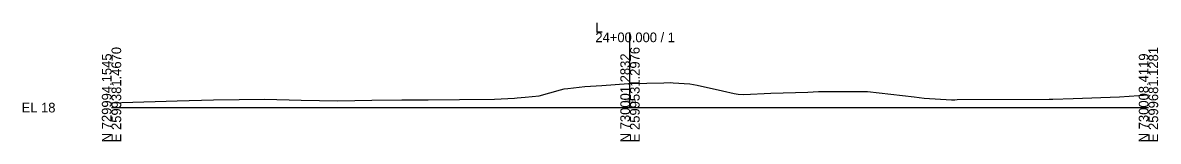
# Model space of a CAD drawing. Extents: x -26 to 3303, y -10 to 9555.
# Drawn here: x 1974.3 to 2302.8, y 7990.3 to 8024.5 of the extents above; entities that cross this region are included whole.
import ezdxf

# ---------------------------------------------------------------- set-up
doc = ezdxf.new("R2010")
doc.units = 0
for name, color, linetype in [('Exist Cross Section Cell', 7, 'Continuous'), ('Exist XS Center Line Elevation Label', 7, 'Continuous'), ('Exist XS Ground Line', 7, 'Continuous')]:
    doc.layers.add(name, color=color, linetype=linetype)

msp = doc.modelspace()

# ---------------------------------------------------------------- linework, layer by layer
at = {"layer": 'Exist Cross Section Cell'}
for p, q in [((2150, 8000), (2150, 8021.65)), ((2000, 8000), (2150, 8000)), ((2150, 8000), (2300, 8000))]:
    msp.add_line(p, q, dxfattribs=at)
at = {"layer": 'Exist XS Ground Line'}
msp.add_lwpolyline([(2000, 8001.36), (2003.01, 8001.47), (2019.03, 8001.96), (2029.54, 8002.27), (2044.36, 8002.41), (2054.86, 8002.14), (2065.49, 8001.95), (2075.31, 8002.1), (2083.97, 8002.24), (2091.59, 8002.25), (2100.67, 8002.29), (2110.77, 8002.46), (2116.63, 8002.72), (2117.38, 8002.77), (2119.63, 8003.01), (2123.74, 8003.41), (2129.89, 8005.1), (2130.93, 8005.38), (2131.97, 8005.52), (2136.97, 8006.06), (2141.83, 8006.33), (2149.6, 8006.92), (2150, 8006.93), (2159.75, 8007.18), (2161.61, 8007.22), (2162.53, 8007.17), (2167.29, 8006.86), (2169.4, 8006.49), (2176.76, 8004.84), (2180.09, 8004.08), (2181.34, 8003.85), (2182.95, 8003.77), (2190.75, 8004.14), (2201.47, 8004.41), (2204.53, 8004.63), (2206.53, 8004.68), (2217.04, 8004.67), (2218.67, 8004.66), (2232.22, 8003.09), (2235.1, 8002.69), (2243, 8002.26), (2243.98, 8002.27), (2244.61, 8002.3), (2271.25, 8002.43), (2272.29, 8002.39), (2278.25, 8002.59), (2291.58, 8003.11), (2300, 8003.71)], dxfattribs=at)

# ---------------------------------------------------------------- texts
at = {"layer": 'Exist Cross Section Cell'}
for s, p in [('L', (2140, 8021.65)), ('24+00.000 / 1', (2140, 8018.85)), ('EL 18', (1974, 7998.6))]:
    msp.add_text(s, height=2.8, dxfattribs=at).set_placement(p)
for s, p in [('E 2599381.4670', (2002.8, 7990)), ('E 2599531.2976', (2152.8, 7990)), ('E 2599681.1281', (2302.8, 7990)), ('N 729994.1545', (2000, 7990)), ('N 730001.2832', (2150, 7990)), ('N 730008.4119', (2300, 7990))]:
    msp.add_text(s, height=2.8, rotation=90, dxfattribs=at).set_placement(p)
at = {"layer": 'Exist XS Center Line Elevation Label'}
msp.add_text('24.93', height=1, dxfattribs=at).set_placement((2148.27, 8001.43))

doc.saveas('drawing.dxf')
